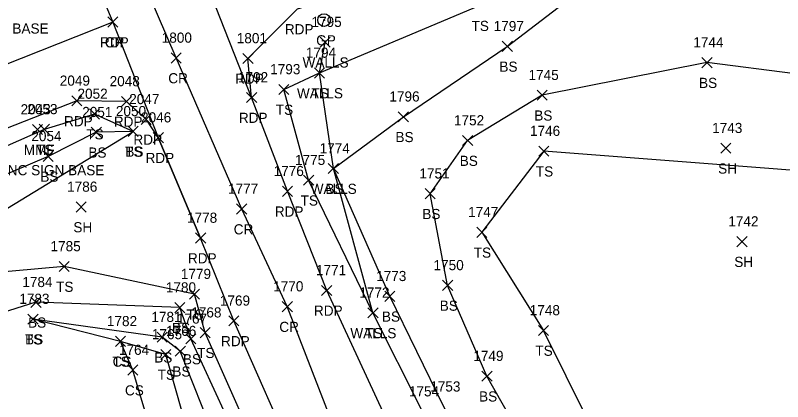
# Model space of a CAD drawing. Extents: x 1472233 to 1475777, y 540726 to 543442.
# Drawn here: x 1475041.4 to 1475192.5, y 543160.9 to 543237 of the extents above; entities that cross this region are included whole.
import ezdxf

# ---------------------------------------------------------------- set-up
doc = ezdxf.new("R2010")
doc.units = 0
for name, color, linetype in [('L_A', 7, 'Continuous'), ('L_C', 7, 'Continuous'), ('L_I', 7, 'Continuous'), ('L_TIC', 7, 'Continuous'), ('LELB', 7, 'Continuous'), ('LWS', 7, 'Continuous'), ('P_A', 7, 'Continuous'), ('P_I', 7, 'Continuous'), ('P_TIC', 7, 'Continuous'), ('PET', 7, 'Continuous'), ('PRC', 7, 'Continuous'), ('R_A', 7, 'Continuous'), ('RGP', 7, 'Continuous')]:
    doc.layers.add(name, color=color, linetype=linetype)

msp = doc.modelspace()

# ---------------------------------------------------------------- linework, layer by layer
at = {"layer": 'L_TIC'}
for points in [[(1475101.39, 543230.76), (1475103.39, 543232.76)], [(1475103.39, 543230.76), (1475101.39, 543232.76)], [(1475137.26, 543229.93), (1475139.26, 543231.93)], [(1475139.26, 543229.93), (1475137.26, 543231.93)], [(1475176.58, 543226.73), (1475178.58, 543228.73)], [(1475178.58, 543226.73), (1475176.58, 543228.73)], [(1475100.29, 543224.69), (1475102.29, 543226.69)], [(1475102.29, 543224.69), (1475100.29, 543226.69)], [(1475100.29, 543224.69), (1475102.29, 543226.69)], [(1475102.29, 543224.69), (1475100.29, 543226.69)], [(1475093.26, 543221.44), (1475095.26, 543223.44)], [(1475095.26, 543221.44), (1475093.26, 543223.44)], [(1475144.13, 543220.3), (1475146.13, 543222.3)], [(1475146.13, 543220.3), (1475144.13, 543222.3)], [(1475055.95, 543216.6), (1475057.95, 543218.6)], [(1475057.95, 543216.6), (1475055.95, 543218.6)], [(1475116.79, 543216.06), (1475118.79, 543218.06)], [(1475118.79, 543216.06), (1475116.79, 543218.06)], [(1475044.74, 543213.53), (1475046.74, 543215.53)], [(1475046.74, 543213.53), (1475044.74, 543215.53)], [(1475046.07, 543213.57), (1475048.07, 543215.57)], [(1475048.07, 543213.57), (1475046.07, 543215.57)], [(1475056.32, 543213), (1475058.32, 543215)], [(1475058.32, 543213), (1475056.32, 543215)], [(1475063.59, 543213.18), (1475065.59, 543215.18)], [(1475065.59, 543213.18), (1475063.59, 543215.18)], [(1475063.59, 543213.18), (1475065.59, 543215.18)], [(1475065.59, 543213.18), (1475063.59, 543215.18)], [(1475129.45, 543211.37), (1475131.45, 543213.37)], [(1475131.45, 543211.37), (1475129.45, 543213.37)], [(1475129.45, 543211.37), (1475131.45, 543213.37)], [(1475131.45, 543211.37), (1475129.45, 543213.37)], [(1475180.29, 543209.85), (1475182.29, 543211.85)], [(1475182.29, 543209.85), (1475180.29, 543211.85)], [(1475144.47, 543209.28), (1475146.47, 543211.28)], [(1475146.47, 543209.28), (1475144.47, 543211.28)], [(1475046.85, 543208.25), (1475048.85, 543210.25)], [(1475048.85, 543208.25), (1475046.85, 543210.25)], [(1475103, 543205.85), (1475105, 543207.85)], [(1475105, 543205.85), (1475103, 543207.85)], [(1475103, 543205.85), (1475105, 543207.85)], [(1475105, 543205.85), (1475103, 543207.85)], [(1475098.14, 543203.55), (1475100.14, 543205.55)], [(1475100.14, 543203.55), (1475098.14, 543205.55)], [(1475122.08, 543200.89), (1475124.08, 543202.89)], [(1475124.08, 543200.89), (1475122.08, 543202.89)], [(1475053.32, 543198.28), (1475055.32, 543200.28)], [(1475055.32, 543198.28), (1475053.32, 543200.28)], [(1475132.24, 543193.28), (1475134.24, 543195.28)], [(1475134.24, 543193.28), (1475132.24, 543195.28)], [(1475183.47, 543191.45), (1475185.47, 543193.45)], [(1475185.47, 543191.45), (1475183.47, 543193.45)], [(1475049.99, 543186.55), (1475051.99, 543188.55)], [(1475051.99, 543186.55), (1475049.99, 543188.55)], [(1475125.51, 543182.82), (1475127.51, 543184.82)], [(1475127.51, 543182.82), (1475125.51, 543184.82)], [(1475075.67, 543181.09), (1475077.67, 543183.09)], [(1475077.67, 543181.09), (1475075.67, 543183.09)], [(1475114.12, 543180.67), (1475116.12, 543182.67)], [(1475116.12, 543180.67), (1475114.12, 543182.67)], [(1475044.44, 543179.49), (1475046.44, 543181.49)], [(1475046.44, 543179.49), (1475044.44, 543181.49)], [(1475072.78, 543178.43), (1475074.78, 543180.43)], [(1475074.78, 543178.43), (1475072.78, 543180.43)], [(1475110.81, 543177.41), (1475112.81, 543179.41)], [(1475112.81, 543177.41), (1475110.81, 543179.41)], [(1475110.81, 543177.41), (1475112.81, 543179.41)], [(1475112.81, 543177.41), (1475110.81, 543179.41)], [(1475043.84, 543176.18), (1475045.84, 543178.18)], [(1475045.84, 543176.18), (1475043.84, 543178.18)], [(1475043.84, 543176.18), (1475045.84, 543178.18)], [(1475045.84, 543176.18), (1475043.84, 543178.18)], [(1475144.38, 543173.94), (1475146.38, 543175.94)], [(1475146.38, 543173.94), (1475144.38, 543175.94)], [(1475144.38, 543173.94), (1475146.38, 543175.94)], [(1475146.38, 543173.94), (1475144.38, 543175.94)], [(1475069.29, 543172.61), (1475071.29, 543174.61)], [(1475071.29, 543172.61), (1475069.29, 543174.61)], [(1475074.93, 543172.27), (1475076.93, 543174.27)], [(1475076.93, 543172.27), (1475074.93, 543174.27)], [(1475077.76, 543173.5), (1475079.76, 543175.5)], [(1475079.76, 543173.5), (1475077.76, 543175.5)], [(1475061.09, 543171.79), (1475063.09, 543173.79)], [(1475063.09, 543171.79), (1475061.09, 543173.79)], [(1475061.09, 543171.79), (1475063.09, 543173.79)], [(1475063.09, 543171.79), (1475061.09, 543173.79)], [(1475070, 543169.21), (1475072, 543171.21)], [(1475072, 543169.21), (1475070, 543171.21)], [(1475072.86, 543169.85), (1475074.86, 543171.85)], [(1475074.86, 543169.85), (1475072.86, 543171.85)], [(1475063.52, 543166.13), (1475065.52, 543168.13)], [(1475065.52, 543166.13), (1475063.52, 543168.13)], [(1475133.26, 543164.93), (1475135.26, 543166.93)], [(1475135.26, 543164.93), (1475133.26, 543166.93)]]:
    msp.add_lwpolyline(points, dxfattribs=at)
at = {"layer": 'LELB'}
for points in [[(1475201.2, 542962.5), (1475181, 543011.96), (1475161.11, 543060.2), (1475139.99, 543118.72), (1475121.58, 543158.94), (1475111.81, 543178.41), (1475099.14, 543204.55), (1475094.26, 543222.44), (1475101.29, 543225.69), (1475132.81, 543238.96), (1475154.58, 543252.15), (1475203.22, 543262.61)], [(1475357.79, 542598.07), (1475337.62, 542645.37), (1475320.89, 542687.95), (1475305.38, 542735.27), (1475286.48, 542775.3), (1475263.86, 542825.53), (1475247.78, 542864.98), (1475221.45, 542921), (1475204.55, 542963.46), (1475185.95, 543014.43), (1475167.08, 543062.79), (1475146.02, 543122.64), (1475125.78, 543159.9), (1475115.12, 543181.67), (1475104, 543206.85), (1475117.79, 543217.06), (1475138.26, 543230.93), (1475159.43, 543247.18), (1475205.28, 543252.38), (1475241.74, 543258.24), (1475252.93, 543261.2)], [(1475351.79, 542648.85), (1475354.21, 542700.68), (1475359.1, 542754.23), (1475365.39, 542809), (1475353.96, 542862.01), (1475341.44, 542908.94), (1475326.71, 542945.92), (1475320.21, 542980.33), (1475313.2, 543006.73), (1475301.5, 543020.23), (1475276.06, 543044.38), (1475278.13, 543102.62), (1475267.62, 543150.84), (1475263.86, 543210.05), (1475244.31, 543220.04), (1475212.37, 543223.3), (1475177.58, 543227.73), (1475145.13, 543221.3), (1475130.45, 543212.37)], [(1475195.05, 542907.44), (1475188.13, 542922.31), (1475175.95, 542951.1), (1475155.33, 542999.19), (1475135.32, 543048.1), (1475107.08, 543104), (1475091.84, 543145.04), (1475078.76, 543174.5), (1475076.67, 543182.09), (1475050.99, 543187.55), (1475025.34, 543185.25), (1475000.68, 543175.19), (1475064.59, 543214.18), (1475056.95, 543217.6), (1475047.07, 543214.57), (1475009.95, 543198.21), (1474965.05, 543179.94), (1474931.5, 543160.66), (1474909.23, 543140.97), (1474878.94, 543098.75), (1474856.03, 543062.59), (1474841.97, 543016.84), (1474822.92, 542953.7), (1474810.37, 542904.9)], [(1475064.59, 543214.18), (1475057.32, 543214), (1475047.85, 543209.25), (1475012.35, 543194.1), (1474968.32, 543171.94), (1474937.2, 543150.94), (1474916.96, 543130.44), (1474889.05, 543091.21), (1474866.44, 543057.27), (1474852.21, 543012.22), (1474834.71, 542948.13), (1474823.88, 542898.3)], [(1475190.59, 543034.86), (1475181.57, 543071.36), (1475156.67, 543126.35), (1475134.26, 543165.93), (1475126.51, 543183.82), (1475123.08, 543201.89), (1475130.45, 543212.37)], [(1475260.95, 543099.97), (1475247.67, 543147.9), (1475249.95, 543204.31), (1475207.64, 543205.47), (1475145.47, 543210.28), (1475133.24, 543194.28), (1475145.38, 543174.94)], [(1475324.25, 542586.46), (1475305.93, 542636.69), (1475289.42, 542677.22), (1475270.47, 542721), (1475249.52, 542773.39), (1475234.34, 542810.62), (1475215.39, 542852.4), (1475193.59, 542906.64), (1475186.62, 542921.79), (1475174.11, 542950.33), (1475153.39, 542998.42), (1475132.78, 543047.28), (1475103.54, 543102.91), (1475089.72, 543143.3), (1475075.93, 543173.27), (1475073.78, 543179.43), (1475045.44, 543180.49), (1475026.91, 543174.69), (1475000.68, 543175.19), (1474987.24, 543167.85), (1474972.18, 543161.15)], [(1475189.29, 542906.29), (1475183.55, 542919.91), (1475172.16, 542949.7), (1475150.99, 542997.15), (1475128.67, 543044.94), (1475101.07, 543101.78), (1475085.31, 543141.92), (1475073.86, 543170.85), (1475070.29, 543173.61), (1475044.84, 543177.18)], [(1475159.21, 542969.58), (1475148.7, 542996.44), (1475121.23, 543042.42), (1475096.84, 543100.02), (1475079.46, 543140.39), (1475071, 543170.21), (1475062.09, 543172.79), (1475044.84, 543177.18)], [(1475199.93, 543045.48), (1475188.19, 543074.86), (1475167.63, 543130.05), (1475145.38, 543174.94)], [(1475159.21, 542969.58), (1475142.51, 542993.57), (1475110.17, 543038.51), (1475089.55, 543096.78), (1475072.82, 543139.08), (1475064.52, 543167.13), (1475062.09, 543172.79)]]:
    msp.add_lwpolyline(points, dxfattribs=at)
at = {"layer": 'LWS'}
msp.add_lwpolyline([(1475111.81, 543178.41), (1475104, 543206.85), (1475101.29, 543225.69), (1475102.39, 543231.76)], dxfattribs=at)
at = {"layer": 'P_TIC'}
for points in [[(1475059.57, 543234.73), (1475061.57, 543236.73)], [(1475061.57, 543234.73), (1475059.57, 543236.73)], [(1475059.57, 543234.73), (1475061.57, 543236.73)], [(1475061.57, 543234.73), (1475059.57, 543236.73)], [(1475072.06, 543227.65), (1475074.06, 543229.65)], [(1475074.06, 543227.65), (1475072.06, 543229.65)], [(1475086.19, 543227.55), (1475088.19, 543229.55)], [(1475088.19, 543227.55), (1475086.19, 543229.55)], [(1475052.47, 543219.18), (1475054.47, 543221.18)], [(1475054.47, 543219.18), (1475052.47, 543221.18)], [(1475062.28, 543219.08), (1475064.28, 543221.08)], [(1475064.28, 543219.08), (1475062.28, 543221.08)], [(1475086.91, 543219.85), (1475088.91, 543221.85)], [(1475088.91, 543219.85), (1475086.91, 543221.85)], [(1475086.91, 543219.85), (1475088.91, 543221.85)], [(1475088.91, 543219.85), (1475086.91, 543221.85)], [(1475066.14, 543215.55), (1475068.14, 543217.55)], [(1475068.14, 543215.55), (1475066.14, 543217.55)], [(1475068.52, 543211.94), (1475070.52, 543213.94)], [(1475070.52, 543211.94), (1475068.52, 543213.94)], [(1475068.52, 543211.94), (1475070.52, 543213.94)], [(1475070.52, 543211.94), (1475068.52, 543213.94)], [(1475093.98, 543201.37), (1475095.98, 543203.37)], [(1475095.98, 543201.37), (1475093.98, 543203.37)], [(1475084.95, 543197.87), (1475086.95, 543199.87)], [(1475086.95, 543197.87), (1475084.95, 543199.87)], [(1475076.87, 543192.16), (1475078.87, 543194.16)], [(1475078.87, 543192.16), (1475076.87, 543194.16)], [(1475101.69, 543181.83), (1475103.69, 543183.83)], [(1475103.69, 543181.83), (1475101.69, 543183.83)], [(1475093.93, 543178.64), (1475095.93, 543180.64)], [(1475095.93, 543178.64), (1475093.93, 543180.64)], [(1475083.39, 543175.83), (1475085.39, 543177.83)], [(1475085.39, 543175.83), (1475083.39, 543177.83)]]:
    msp.add_lwpolyline(points, dxfattribs=at)
at = {"layer": 'PET'}
for points in [[(1475087.91, 543220.85), (1475087.19, 543228.55), (1475096.96, 543238.31), (1475120.81, 543245.65), (1475153.05, 543255.59), (1475202.33, 543267.68), (1475249.58, 543276.45), (1475275.49, 543280.28), (1475323.7, 543287.39), (1475369.23, 543294.1), (1475413.44, 543300.77), (1475466.08, 543307.86)], [(1475115.44, 543155.27), (1475102.69, 543182.83), (1475094.98, 543202.37), (1475087.91, 543220.85), (1475079.2, 543242.94), (1475068.73, 543266.37)], [(1475055.67, 543247.46), (1475060.57, 543235.73), (1475069.52, 543212.94)], [(1475097.32, 543147.51), (1475084.39, 543176.83), (1475077.87, 543193.16), (1475069.52, 543212.94), (1475067.14, 543216.55), (1475063.28, 543220.08), (1475053.47, 543220.18), (1475008.24, 543202.49), (1474964.19, 543183.68), (1474928.03, 543165.54), (1474904.75, 543147.48), (1474872.73, 543104), (1474852.33, 543065.67), (1474835.49, 543020.36), (1474817.49, 542956.59), (1474804.28, 542907.81)], [(1475069.52, 543212.94), (1475077.87, 543193.16)]]:
    msp.add_lwpolyline(points, dxfattribs=at)
at = {"layer": 'PRC'}
for points in [[(1475340.99, 542592.55), (1475321.95, 542640.5), (1475304.24, 542682.02), (1475285.94, 542727.1), (1475264.52, 542778.11), (1475248.03, 542818.3), (1475231.01, 542858.29), (1475206.98, 542914.26), (1475189.62, 542957.63), (1475167.76, 543005.52), (1475147.33, 543055.02), (1475123.61, 543111.78), (1475106.14, 543150.71), (1475094.93, 543179.64), (1475085.95, 543198.87), (1475073.06, 543228.65), (1475063.84, 543250.07), (1475052.92, 543275.83), (1475038.81, 543308.89), (1475018.14, 543355.82)], [(1475060.57, 543235.73), (1475003.22, 543212.97), (1474958.58, 543194.55), (1474921.88, 543175.73), (1474897.82, 543157.54), (1474862.69, 543111.06), (1474841.92, 543071.62), (1474824.62, 543025.61), (1474806.27, 542961.11), (1474792.96, 542911.81)]]:
    msp.add_lwpolyline(points, dxfattribs=at)
at = {"layer": 'RGP'}
msp.add_line((1475102.18, 543236.12), (1475102.18, 543236.12), dxfattribs=at)
for radius in [1.25, 0.0833]:
    msp.add_circle((1475102.18, 543236.12), radius, dxfattribs=at)

# ---------------------------------------------------------------- texts
at = {"layer": 'L_A'}
for s, p in [('TS', (1475131.22, 543233.96)), ('WALLS', (1475097.94, 543226.76)), ('BS', (1475136.7, 543225.93)), ('BS', (1475176.02, 543222.73)), ('WALLS', (1475096.83, 543220.69)), ('TS', (1475099.7, 543220.69)), ('TS', (1475092.67, 543217.44)), ('BS', (1475143.57, 543216.3)), ('TS', (1475055.36, 543212.6)), ('BS', (1475116.23, 543212.06)), ('MMF', (1475043.03, 543209.53)), ('TS', (1475045.48, 543209.57)), ('BS', (1475055.76, 543209)), ('TS', (1475063, 543209.18)), ('BS', (1475063.04, 543209.18)), ('BS', (1475128.89, 543207.37)), ('BS', (1475128.89, 543207.37)), ('TS', (1475143.88, 543205.28)), ('SH', (1475179.78, 543205.85)), ('BS', (1475046.3, 543204.25)), ('WALLS', (1475099.54, 543201.85)), ('BS', (1475102.44, 543201.85)), ('TS', (1475097.55, 543199.55)), ('BS', (1475121.52, 543196.89)), ('SH', (1475052.8, 543194.28)), ('TS', (1475131.65, 543189.28)), ('SH', (1475182.96, 543187.45)), ('TS', (1475049.4, 543182.55)), ('BS', (1475124.95, 543178.82)), ('TS', (1475075.08, 543177.09)), ('BS', (1475113.56, 543176.67)), ('BS', (1475043.88, 543175.49)), ('BS', (1475072.23, 543174.43)), ('TS', (1475043.25, 543172.18)), ('BS', (1475043.29, 543172.18)), ('WALLS', (1475107.35, 543173.41)), ('TS', (1475110.22, 543173.41)), ('TS', (1475077.17, 543169.5)), ('TS', (1475143.79, 543169.94)), ('TS', (1475143.79, 543169.94)), ('TS', (1475060.5, 543167.79)), ('CS', (1475060.54, 543167.79)), ('BS', (1475068.73, 543168.61)), ('BS', (1475074.37, 543168.27)), ('TS', (1475069.41, 543165.21)), ('BS', (1475072.3, 543165.85)), ('CS', (1475062.96, 543162.13)), ('BS', (1475132.7, 543160.93))]:
    msp.add_text(s, height=2, dxfattribs=at).set_placement(p)
at = {"layer": 'L_C'}
for p in [(1475018.65, 543233.45), (1475029.63, 543205.53)]:
    msp.add_text('OLD CONC SIGN BASE', height=2, dxfattribs=at).set_placement(p)
at = {"layer": 'L_I'}
for s, p in [('1795', (1475099.7, 543234.76)), ('1797', (1475135.57, 543233.93)), ('1744', (1475174.89, 543230.73)), ('1794', (1475098.59, 543228.69)), ('1794', (1475098.59, 543228.69)), ('1793', (1475091.56, 543225.44)), ('1745', (1475142.44, 543224.3)), ('2052', (1475053.61, 543220.6)), ('1796', (1475115.04, 543220.06)), ('2043', (1475042.4, 543217.53)), ('2053', (1475043.73, 543217.57)), ('2051', (1475054.54, 543217)), ('2050', (1475061.17, 543217.18)), ('2050', (1475061.17, 543217.18)), ('1752', (1475127.75, 543215.37)), ('1752', (1475127.75, 543215.37)), ('1746', (1475142.72, 543213.28)), ('1743', (1475178.6, 543213.85)), ('2054', (1475044.52, 543212.25)), ('1774', (1475101.3, 543209.85)), ('1774', (1475101.3, 543209.85)), ('1775', (1475096.45, 543207.55)), ('1751', (1475120.95, 543204.89)), ('1786', (1475051.57, 543202.28)), ('1747', (1475130.54, 543197.28)), ('1742', (1475181.78, 543195.45)), ('1785', (1475048.3, 543190.55)), ('1750', (1475123.73, 543186.82)), ('1779', (1475073.97, 543185.09)), ('1773', (1475112.43, 543184.67)), ('1784', (1475042.75, 543183.49)), ('1780', (1475071.01, 543182.43)), ('1772', (1475109.11, 543181.41)), ('1772', (1475109.11, 543181.41)), ('1783', (1475042.15, 543180.18)), ('1783', (1475042.15, 543180.18)), ('1781', (1475068.17, 543176.61)), ('1768', (1475076.02, 543177.5)), ('1748', (1475142.68, 543177.94)), ('1748', (1475142.68, 543177.94)), ('1782', (1475059.4, 543175.79)), ('1782', (1475059.4, 543175.79)), ('1767', (1475073.19, 543176.27)), ('1766', (1475071.06, 543173.85)), ('1765', (1475068.26, 543173.21)), ('1764', (1475061.78, 543170.13)), ('1749', (1475131.56, 543168.93)), ('1754', (1475118.88, 543161.94)), ('1753', (1475123.08, 543162.9))]:
    msp.add_text(s, height=2, dxfattribs=at).set_placement(p)
at = {"layer": 'P_A'}
for s, p in [('RDP', (1475094.45, 543233.31)), ('RDP', (1475058.05, 543230.73)), ('CR', (1475059, 543230.73)), ('CR', (1475071.49, 543223.65)), ('RDP', (1475084.67, 543223.55)), ('RDP', (1475085.39, 543215.85)), ('RDP', (1475085.39, 543215.85)), ('RDP', (1475050.96, 543215.18)), ('RDP', (1475060.77, 543215.08)), ('RDP', (1475064.63, 543211.55)), ('RDP', (1475067.01, 543207.94)), ('RDP', (1475067.01, 543207.94)), ('RDP', (1475092.47, 543197.37)), ('CR', (1475084.38, 543193.87)), ('RDP', (1475075.36, 543188.16)), ('RDP', (1475100.18, 543177.83)), ('CR', (1475093.36, 543174.64)), ('RDP', (1475081.88, 543171.83))]:
    msp.add_text(s, height=2, dxfattribs=at).set_placement(p)
at = {"layer": 'P_I'}
for s, p in [('1800', (1475070.2, 543231.65)), ('1801', (1475084.98, 543231.55)), ('1792', (1475085.21, 543223.85)), ('1792', (1475085.21, 543223.85)), ('2049', (1475050.12, 543223.18)), ('2048', (1475059.94, 543223.08)), ('2047', (1475063.8, 543219.55)), ('2046', (1475066.13, 543215.94)), ('2046', (1475066.13, 543215.94)), ('1776', (1475092.24, 543205.37)), ('1777', (1475083.25, 543201.87)), ('1778', (1475075.18, 543196.16)), ('1771', (1475100.57, 543185.83)), ('1770', (1475092.15, 543182.64)), ('1769', (1475081.65, 543179.83))]:
    msp.add_text(s, height=2, dxfattribs=at).set_placement(p)
at = {"layer": 'R_A'}
msp.add_text('GP', height=2, dxfattribs=at).set_placement((1475100.62, 543231.12))

doc.saveas('drawing.dxf')
